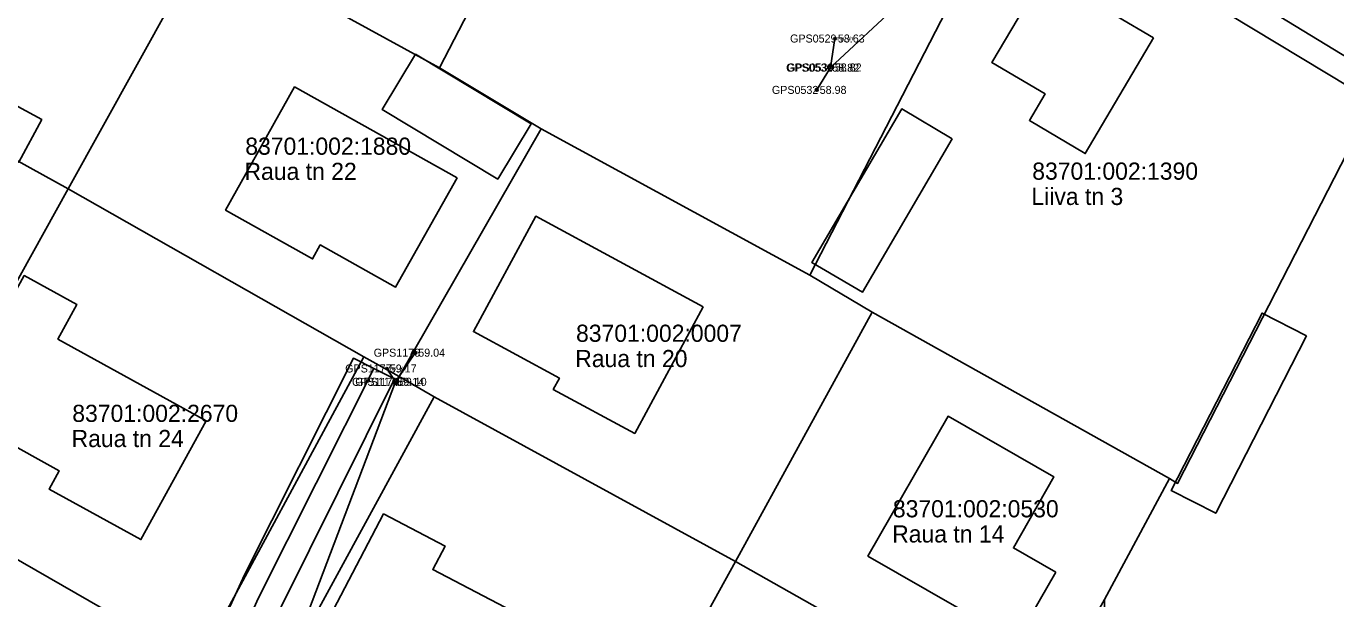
# Model space of a CAD drawing. Extents: x 580119 to 583377, y 6518915 to 6520820.
# Drawn here: x 581946.3 to 582060.9, y 6520050.4 to 6520100.4 of the extents above; entities that cross this region are included whole.
import ezdxf

# ---------------------------------------------------------------- set-up
doc = ezdxf.new("R2010")
doc.units = 0
for name, color, linetype in [('Hoone Elu- või ühiskondlik hoone', 7, 'Continuous'), ('Hoone Kõrval- või tootmishoone', 7, 'Continuous'), ('L_AADRESS', 7, 'Continuous'), ('MAAMUDEL', 7, 'Continuous'), ('MOOTKORG-EH2000', 7, 'Continuous'), ('MOOTMPUNKT', 7, 'Continuous'), ('MOOTNR', 7, 'Continuous'), ('MPOHULIIN', 7, 'Continuous'), ('PIIR', 7, 'Continuous'), ('POST', 7, 'Continuous'), ('Tee Liiklusala', 7, 'Continuous'), ('Tee Tänav Kruuskate', 7, 'Continuous'), ('TUNNUS', 7, 'Continuous')]:
    doc.layers.add(name, color=color, linetype=linetype)

msp = doc.modelspace()

# ---------------------------------------------------------------- linework, layer by layer
at = {"layer": 'Hoone Elu- või ühiskondlik hoone'}
for points in [[(582044.92, 6520099.4), (582038.96, 6520089.29), (582034.07, 6520092.18), (582035.44, 6520094.5), (582030.78, 6520097.25), (582035.38, 6520105.03)], [(581984.01, 6520087.15), (581978.64, 6520077.61), (581972.05, 6520081.3), (581971.37, 6520080.08), (581963.76, 6520084.35), (581969.8, 6520095.11)], [(582005.53, 6520075.88), (581999.55, 6520064.82), (581992.43, 6520068.67), (581992.96, 6520069.65), (581985.44, 6520073.72), (581990.89, 6520083.8)], [(581962.07, 6520065.92), (581956.36, 6520055.54), (581948.33, 6520059.96), (581949.2, 6520061.56), (581943.99, 6520064.43), (581943.19, 6520062.99), (581938.87, 6520065.37), (581946.16, 6520078.62), (581950.76, 6520076.09), (581949.1, 6520073.07)], [(582036.39, 6520052.69), (582032.92, 6520046.66), (582019.95, 6520054.11), (582026.96, 6520066.32), (582036.22, 6520061.02), (582032.67, 6520054.82)], [(581972.51, 6520048.1), (581977.58, 6520057.79), (581982.96, 6520054.98), (581981.88, 6520052.92), (581993.89, 6520046.67), (581988.95, 6520037.19), (581974.44, 6520044.75), (581975.4, 6520046.59)]]:
    msp.add_lwpolyline(points, close=True, dxfattribs=at)
at = {"layer": 'Hoone Kõrval- või tootmishoone'}
for points in [[(581990.49, 6520091.88), (581987.57, 6520087.05), (581977.45, 6520093.14), (581980.37, 6520097.97)], [(581939.03, 6520092.1), (581941.04, 6520095.84), (581947.69, 6520092.26), (581945.68, 6520088.52)], [(582027.33, 6520090.58), (582019.47, 6520077.17), (582015.03, 6520079.77), (582022.9, 6520093.19)], [(582058.32, 6520073.35), (582050.37, 6520057.84), (582046.48, 6520059.83), (582054.42, 6520075.34)]]:
    msp.add_lwpolyline(points, close=True, dxfattribs=at)
at = {"layer": 'MOOTMPUNKT'}
for centre in [(582017.06, 6520099.34), (582016.57, 6520096.79), (582016.79, 6520096.81), (582015.47, 6520094.85), (581980.36, 6520071.88), (581977.87, 6520070.5), (581978.53, 6520069.33), (581978.75, 6520069.34)]:
    msp.add_circle(centre, 0.1, dxfattribs=at)
at = {"layer": 'MPOHULIIN'}
msp.add_line((581977.87, 6520070.5), (581978.64, 6520069.34), dxfattribs=at)
for points in [[(582074.17, 6520090.2), (582035.13, 6520113.98), (581994.07, 6520138.74), (581958.9, 6520159.67), (581929.45, 6520177.38), (581899.05, 6520195.29), (581871.11, 6520211.35), (581850.55, 6520223.51), (581830.36, 6520235.9)], [(582035.13, 6520113.98), (582016.68, 6520096.8), (582017.06, 6520099.34)], [(581950.86, 6520007.26), (581951.05, 6520007.82), (581964.38, 6520031.77), (581978.64, 6520069.34)]]:
    msp.add_lwpolyline(points, dxfattribs=at)
at = {"layer": 'PIIR'}
for points in [[(581942.75, 6520182.07), (581974.77, 6520162.07), (582006.04, 6520143.43), (582038.07, 6520123.88), (582050.1, 6520116.94), (582069.55, 6520104.59), (582123.3, 6520072.1), (582120.68, 6520059.28), (582096.36, 6520074.44), (582064.17, 6520093.83), (582032.54, 6520112.93), (582001.15, 6520132.88), (581968.64, 6520151.74), (581937.09, 6520170.6)], [(581935.27, 6520059.68), (581961.38, 6520044.71), (581975.85, 6520071.52), (581978.94, 6520069.81), (581982, 6520068.01), (581967.69, 6520041.77), (581993.62, 6520026.9), (582019.64, 6520012.26), (582034.3, 6520038.98), (582040.64, 6520050.31), (582040.9, 6520034.7), (582025.18, 6520006.25), (582051.72, 6519988.28), (582065.39, 6519977.21), (582060.37, 6519969.9), (582014.59, 6520003.08), (581988.42, 6520017.74), (581962.35, 6520032.18), (581949.86, 6520009.55), (581943.51, 6520012.98), (581956.4, 6520035.78), (581930.04, 6520050.18)]]:
    msp.add_lwpolyline(points, dxfattribs=at)
for points in [[(581949.67, 6520115.03), (581968.64, 6520151.74), (582001.15, 6520132.88), (581982.47, 6520096.79), (581962.08, 6520107.97)], [(581982.47, 6520096.79), (582001.15, 6520132.88), (582032.54, 6520112.93), (582014.86, 6520078.65), (581991.36, 6520091.45)], [(581919.2, 6520103.01), (581920.52, 6520105.4), (581923.44, 6520110.63), (581926.36, 6520115.88), (581931.46, 6520124.92), (581949.67, 6520115.03), (581962.08, 6520107.97), (581949.99, 6520086.2), (581925.66, 6520099.62), (581923.71, 6520100.64)], [(582014.86, 6520078.65), (582032.54, 6520112.93), (582064.17, 6520093.83), (582047.03, 6520060.45), (582046.31, 6520060.89), (582020.31, 6520075.42)], [(581962.08, 6520107.97), (581982.47, 6520096.79), (581991.36, 6520091.45), (581978.94, 6520069.81), (581975.85, 6520071.52), (581949.99, 6520086.2)], [(581935.27, 6520059.68), (581908.98, 6520073.94), (581920.7, 6520095.82), (581925.66, 6520099.62), (581949.99, 6520086.2)], [(582040.64, 6520050.31), (582046.31, 6520060.89), (582047.03, 6520060.45), (582064.17, 6520093.83), (582096.36, 6520074.44), (582074.87, 6520034.25), (582065.39, 6520016.62), (582040.9, 6520034.7)], [(581991.36, 6520091.45), (582014.86, 6520078.65), (582020.31, 6520075.42), (582008.37, 6520053.62), (581982, 6520068.01), (581978.94, 6520069.81)], [(581975.85, 6520071.52), (581961.38, 6520044.71), (581935.27, 6520059.68), (581949.99, 6520086.2)], [(582020.31, 6520075.42), (582046.31, 6520060.89), (582040.64, 6520050.31), (582034.3, 6520038.98), (582008.37, 6520053.62)], [(581982, 6520068.01), (582008.37, 6520053.62), (581993.62, 6520026.9), (581967.69, 6520041.77)], [(582034.3, 6520038.98), (582019.64, 6520012.26), (581993.62, 6520026.9), (582008.37, 6520053.62)]]:
    msp.add_lwpolyline(points, close=True, dxfattribs=at)
at = {"layer": 'POST'}
for points in [[(582016.68, 6520096.8), (582015.47, 6520094.85)], [(581980.36, 6520071.88), (581978.64, 6520069.34)]]:
    msp.add_lwpolyline(points, dxfattribs=at)
for centre, radius in [((582016.68, 6520096.8), 0.25), ((582015.47, 6520094.85), 0.125), ((582015.47, 6520094.85), 0.105), ((582015.47, 6520094.85), 0.0851), ((582015.47, 6520094.85), 0.0651), ((582015.47, 6520094.85), 0.0451), ((582015.47, 6520094.85), 0.0251), ((582015.47, 6520094.85), 0.00511), ((581980.36, 6520071.88), 0.125), ((581980.36, 6520071.88), 0.105), ((581980.36, 6520071.88), 0.0851), ((581980.36, 6520071.88), 0.0651), ((581980.36, 6520071.88), 0.0451), ((581980.36, 6520071.88), 0.0251), ((581980.36, 6520071.88), 0.00511), ((581978.64, 6520069.34), 0.25)]:
    msp.add_circle(centre, radius, dxfattribs=at)
at = {"layer": 'Tee Liiklusala'}
msp.add_lwpolyline([(581962.23, 6520045.52), (581965.43, 6520052.46), (581974.95, 6520071.39), (581976.74, 6520070.49), (581978.53, 6520069.59), (581966.14, 6520044.68)], dxfattribs=at)
at = {"layer": 'Tee Tänav Kruuskate'}
msp.add_lwpolyline([(581961.49, 6520039.04), (581966.64, 6520050.45), (581976.74, 6520070.49)], dxfattribs=at)

# ---------------------------------------------------------------- texts
at = {"layer": 'L_AADRESS'}
for s, p in [('Raua tn 22', (581965.42, 6520086.98)), ('Liiva tn 3', (582034.25, 6520084.79)), ('Raua tn 20', (581994.35, 6520070.62)), ('Raua tn 24', (581950.3, 6520063.63)), ('Raua tn 14', (582022.07, 6520055.29))]:
    msp.add_text(s, height=1.5, dxfattribs=at).set_placement(p)
at = {"layer": 'MAAMUDEL'}
for p in [(582017.06, 6520099.17), (581977.87, 6520070.33)]:
    msp.add_text(' mp_ohl', height=0.35, dxfattribs=at).set_placement(p)
at = {"layer": 'MOOTKORG-EH2000'}
for s, p in [(' 58.63', (582017.06, 6520098.99)), (' 58.82', (582016.57, 6520096.44)), (' 58.82', (582016.79, 6520096.46)), (' 58.98', (582015.47, 6520094.5)), (' 59.04', (581980.36, 6520071.53)), (' 59.17', (581977.87, 6520070.15)), (' 59.14', (581978.53, 6520068.98)), (' 59.10', (581978.75, 6520068.99))]:
    msp.add_text(s, height=0.7, dxfattribs=at).set_placement(p)
at = {"layer": 'MOOTNR'}
for s, p in [('GPS0529 ', (582013.14, 6520098.99)), ('GPS0531 ', (582012.79, 6520096.44)), ('GPS0530 ', (582012.87, 6520096.46)), ('GPS0532 ', (582011.55, 6520094.5)), ('GPS1176 ', (581976.72, 6520071.53)), ('GPS1177 ', (581974.23, 6520070.15)), ('GPS1174 ', (581974.82, 6520068.98)), ('GPS1175 ', (581975.11, 6520068.99))]:
    msp.add_text(s, height=0.7, dxfattribs=at).set_placement(p)
at = {"layer": 'TUNNUS'}
for s, p in [('83701:002:1880', (581965.49, 6520089.18)), ('83701:002:1390', (582034.32, 6520087)), ('83701:002:0007', (581994.42, 6520072.83)), ('83701:002:2670', (581950.36, 6520065.83)), ('83701:002:0530', (582022.13, 6520057.49))]:
    msp.add_text(s, height=1.5, dxfattribs=at).set_placement(p)

doc.saveas('drawing.dxf')
